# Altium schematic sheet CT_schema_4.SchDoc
size 293 x 156 mm
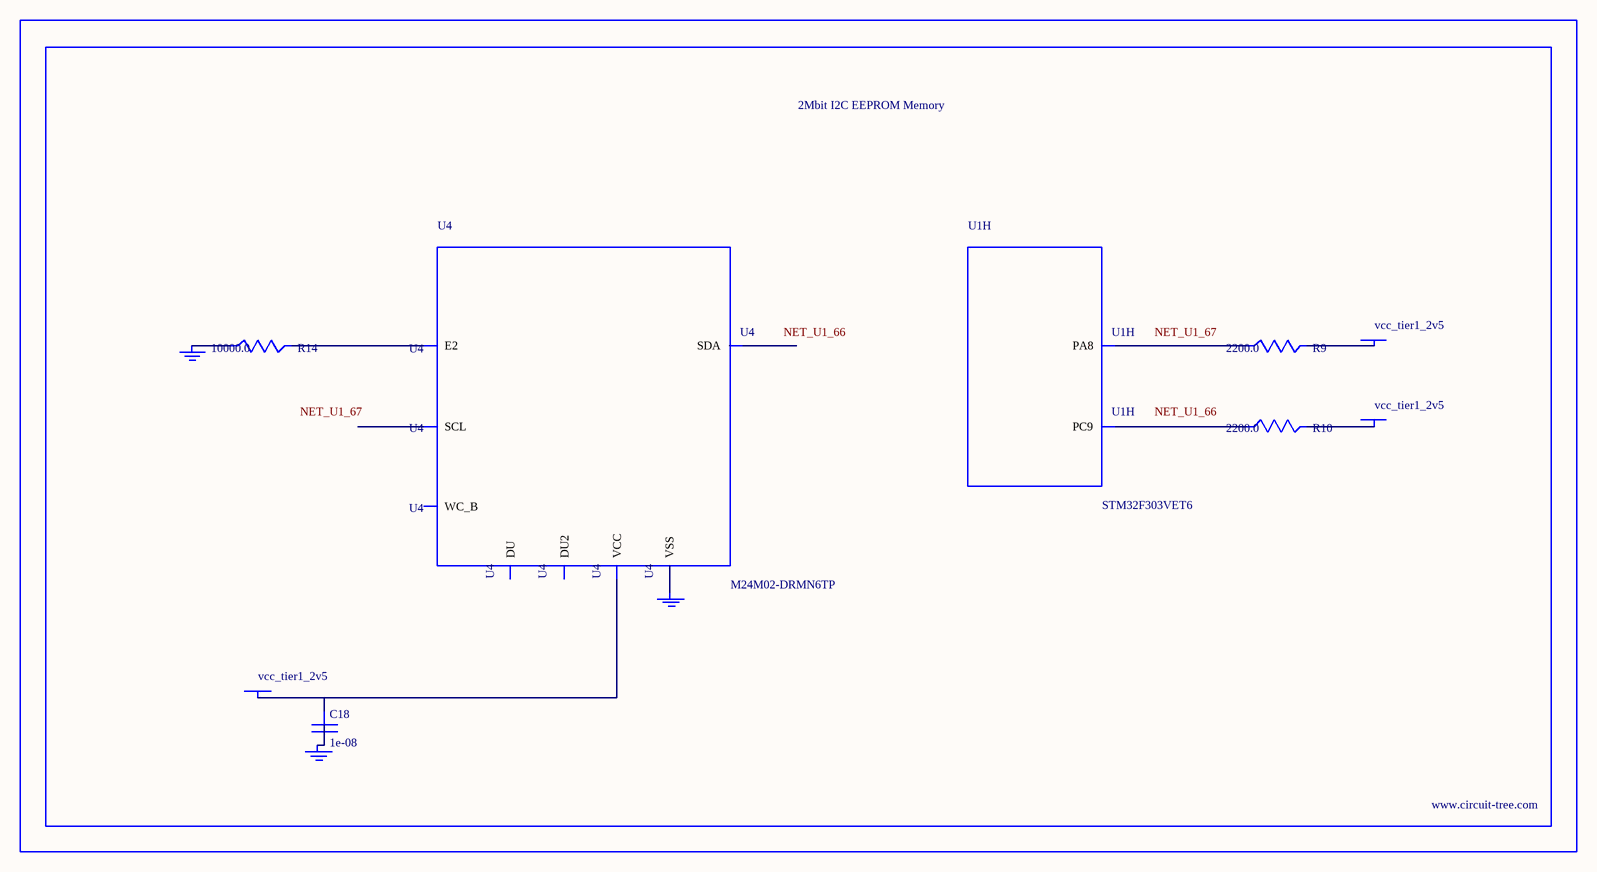
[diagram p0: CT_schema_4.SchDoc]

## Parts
BORDER3  (no value)
C18  1e-08  [C0402]
GND_INSTANCE_3_0  (no value)
GND_INSTANCE_3_1  (no value)
GND_INSTANCE_3_2  (no value)
POWER_INSTANCE_3_0  vcc_tier1_2v5
POWER_INSTANCE_3_1  vcc_tier1_2v5
POWER_INSTANCE_3_2  vcc_tier1_2v5
R9  2200.0  [R0603]
R10  2200.0  [R0603]
R14  10000.0  [R0603]
U1  STM32F303VET6  [LQFP100]  (part H of 9)
U4  M24M02-DRMN6TP  [SOIC-8]

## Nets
NetC18_1: C18.1 POWER_INSTANCE_3_0.0(PWR) U4.8(VCC)
NetC18_2: C18.2 GND_INSTANCE_3_1.0(GND)
NetGND_INSTANCE_3_0_0: GND_INSTANCE_3_0.0(GND) R14.1
NetGND_INSTANCE_3_2_0: GND_INSTANCE_3_2.0(GND) U4.4(VSS)
NetPOWER_INSTANCE_3_1_0: POWER_INSTANCE_3_1.0(PWR) R10.2
NetPOWER_INSTANCE_3_2_0: POWER_INSTANCE_3_2.0(PWR) R9.2
NetR9_1: R9.1 U1.67(PA8)
NetR10_1: R10.1 U1.66(PC9)
NetR14_2: R14.2 U4.3(E2)

Not connected (* = marked no-connect by the designer): U4 1(DU) 2(DU2) 5(SDA) 6(SCL) 7(WC_B)

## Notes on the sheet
- Labels drawn without touching a wire or pin: NET_U1_66, NET_U1_67

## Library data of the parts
BORDER3 = BORDER_PAGE3
C18 = C0402C103K3RAC
GND_INSTANCE_3_0-GND_INSTANCE_3_2 = GND
POWER_INSTANCE_3_0-POWER_INSTANCE_3_2 = PWR
R9 R10 = RC0603JR-072K2L
R14 = RC0603JR-0710KL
